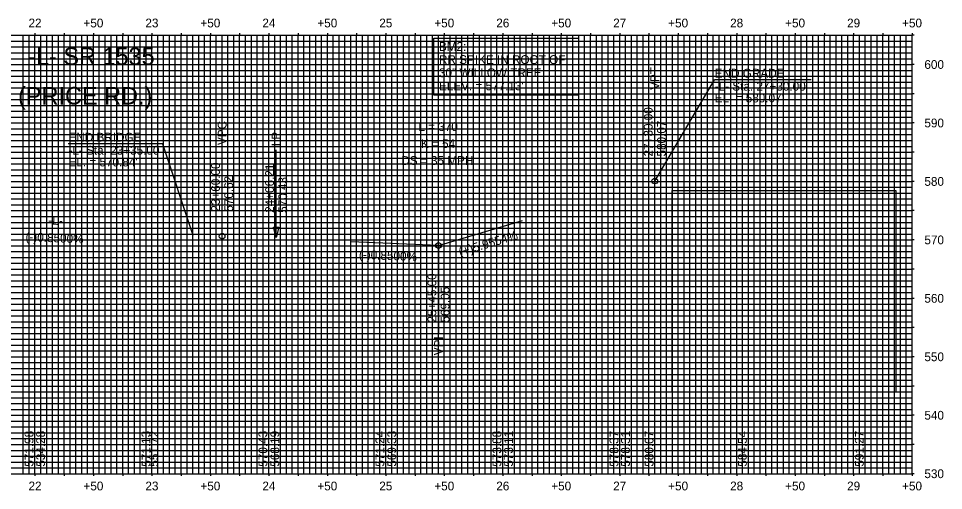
# Model space of a CAD drawing. Extents: x 523 to 1977, y 516 to 919.
# Drawn here: x 1186 to 1977, y 516 to 919 of the extents above; entities that cross this region are included whole.
import ezdxf

# ---------------------------------------------------------------- set-up
doc = ezdxf.new("R2010")
doc.units = 0
for name, color, linetype in [('_CIVIL_CONSTRUCTION', 7, 'Continuous'), ('E_ENV_WETLAND_BOUNDARY', 7, 'Continuous'), ('E_NCDOT_Vertical_Profile_Ground_Line', 7, 'Continuous'), ('Exist Hydro Jurisdictional Stream or Body of Water', 7, 'Continuous'), ('P_NCDOT_Horizontal_Alignment_Curve_and_Spiral_Data', 7, 'Continuous'), ('P_NCDOT_Horizontal_Alignment_Direction_Label', 7, 'Continuous'), ('P_NCDOT_Horizontal_Alignment_Station_Label', 7, 'Continuous'), ('P_NCDOT_Intersecting_Profile', 7, 'Continuous'), ('P_NCDOT_Vertical_Profile_Grade', 7, 'Continuous'), ('Scratch_Level_2', 7, 'Continuous'), ('Scratch_Level_4', 7, 'Continuous')]:
    doc.layers.add(name, color=color, linetype=linetype)

msp = doc.modelspace()

# ---------------------------------------------------------------- linework, layer by layer
at = {"layer": 'E_ENV_WETLAND_BOUNDARY'}
for p, q in [((1730, 780.35), (1781.08, 866.98)), ((1863.58, 866.98), (1781.08, 866.98)), ((1730, 780.35), (1730, 855.35)), ((1308.95, 812.23), (1228.48, 812.23)), ((1308.95, 812.23), (1335.05, 734.18)), ((1360, 733.12), (1360, 808.12)), ((1406.21, 732.14), (1406.21, 807.14)), ((1730, 780.35), (1730, 780.35)), ((1545, 725.26), (1616.88, 746.67)), ((1360, 733.12), (1360, 733.12)), ((1545, 725.26), (1470.07, 728.45)), ((1545, 725.26), (1545, 725.26)), ((1545, 725.26), (1545, 650.26))]:
    msp.add_line(p, q, dxfattribs=at)
for points in [[(1541.14, 902.67), (1664.63, 902.67), (1664.63, 853.75), (1541.14, 853.75)], [(1744.94, 772.35), (1936.19, 772.35), (1936.19, 599.89), (1744.94, 599.89)], [(1406.21, 732.14), (1404.03, 740.87), (1408.4, 740.87)]]:
    msp.add_lwpolyline(points, close=True, dxfattribs=at)
for centre in [(1730, 780.35), (1360, 733.12), (1545, 725.26)]:
    msp.add_circle(centre, 2.43, dxfattribs=at)
at = {"layer": 'E_NCDOT_Vertical_Profile_Ground_Line'}
for p, q in [((1200, 530), (1200, 905)), ((1250, 530), (1250, 905)), ((1300, 530), (1300, 905)), ((1350, 530), (1350, 905)), ((1400, 530), (1400, 905)), ((1450, 530), (1450, 905)), ((1500, 530), (1500, 905)), ((1550, 530), (1550, 905)), ((1600, 530), (1600, 905)), ((1650, 530), (1650, 905)), ((1700, 530), (1700, 905)), ((1750, 530), (1750, 905)), ((1800, 530), (1800, 905)), ((1850, 530), (1850, 905)), ((1900, 530), (1900, 905)), ((550, 880), (1950, 880)), ((550, 830), (1950, 830)), ((550, 780), (1950, 780)), ((550, 730), (1950, 730)), ((550, 680), (1950, 680)), ((550, 630), (1950, 630)), ((550, 580), (1950, 580))]:
    msp.add_line(p, q, dxfattribs=at)
at = {"layer": 'P_NCDOT_Horizontal_Alignment_Curve_and_Spiral_Data'}
for p, q in [((1190, 530), (1190, 905)), ((1195, 530), (1195, 905)), ((1205, 530), (1205, 905)), ((1210, 530), (1210, 905)), ((1215, 530), (1215, 905)), ((1220, 530), (1220, 905)), ((1230, 530), (1230, 905)), ((1235, 530), (1235, 905)), ((1240, 530), (1240, 905)), ((1245, 530), (1245, 905)), ((1255, 530), (1255, 905)), ((1260, 530), (1260, 905)), ((1265, 530), (1265, 905)), ((1270, 530), (1270, 905)), ((1280, 530), (1280, 905)), ((1285, 530), (1285, 905)), ((1290, 530), (1290, 905)), ((1295, 530), (1295, 905)), ((1305, 530), (1305, 905)), ((1310, 530), (1310, 905)), ((1315, 530), (1315, 905)), ((1320, 530), (1320, 905)), ((1330, 530), (1330, 905)), ((1335, 530), (1335, 905)), ((1340, 530), (1340, 905)), ((1345, 530), (1345, 905)), ((1355, 530), (1355, 905)), ((1360, 530), (1360, 905)), ((1365, 530), (1365, 905)), ((1370, 530), (1370, 905)), ((1380, 530), (1380, 905)), ((1385, 530), (1385, 905)), ((1390, 530), (1390, 905)), ((1395, 530), (1395, 905)), ((1405, 530), (1405, 905)), ((1410, 530), (1410, 905)), ((1415, 530), (1415, 905)), ((1420, 530), (1420, 905)), ((1430, 530), (1430, 905)), ((1435, 530), (1435, 905)), ((1440, 530), (1440, 905)), ((1445, 530), (1445, 905)), ((1455, 530), (1455, 905)), ((1460, 530), (1460, 905)), ((1465, 530), (1465, 905)), ((1470, 530), (1470, 905)), ((1480, 530), (1480, 905)), ((1485, 530), (1485, 905)), ((1490, 530), (1490, 905)), ((1495, 530), (1495, 905)), ((1505, 530), (1505, 905)), ((1510, 530), (1510, 905)), ((1515, 530), (1515, 905)), ((1520, 530), (1520, 905)), ((1530, 530), (1530, 905)), ((1535, 530), (1535, 905)), ((1540, 530), (1540, 905)), ((1545, 530), (1545, 905)), ((1555, 530), (1555, 905)), ((1560, 530), (1560, 905)), ((1565, 530), (1565, 905)), ((1570, 530), (1570, 905)), ((1580, 530), (1580, 905)), ((1585, 530), (1585, 905)), ((1590, 530), (1590, 905)), ((1595, 530), (1595, 905)), ((1605, 530), (1605, 905)), ((1610, 530), (1610, 905)), ((1615, 530), (1615, 905)), ((1620, 530), (1620, 905)), ((1630, 530), (1630, 905)), ((1635, 530), (1635, 905)), ((1640, 530), (1640, 905)), ((1645, 530), (1645, 905)), ((1655, 530), (1655, 905)), ((1660, 530), (1660, 905)), ((1665, 530), (1665, 905)), ((1670, 530), (1670, 905)), ((1680, 530), (1680, 905)), ((1685, 530), (1685, 905)), ((1690, 530), (1690, 905)), ((1695, 530), (1695, 905)), ((1705, 530), (1705, 905)), ((1710, 530), (1710, 905)), ((1715, 530), (1715, 905)), ((1720, 530), (1720, 905)), ((1730, 530), (1730, 905)), ((1735, 530), (1735, 905)), ((1740, 530), (1740, 905)), ((1745, 530), (1745, 905)), ((1755, 530), (1755, 905)), ((1760, 530), (1760, 905)), ((1765, 530), (1765, 905)), ((1770, 530), (1770, 905)), ((1780, 530), (1780, 905)), ((1785, 530), (1785, 905)), ((1790, 530), (1790, 905)), ((1795, 530), (1795, 905)), ((1805, 530), (1805, 905)), ((1810, 530), (1810, 905)), ((1815, 530), (1815, 905)), ((1820, 530), (1820, 905)), ((1830, 530), (1830, 905)), ((1835, 530), (1835, 905)), ((1840, 530), (1840, 905)), ((1845, 530), (1845, 905)), ((1855, 530), (1855, 905)), ((1860, 530), (1860, 905)), ((1865, 530), (1865, 905)), ((1870, 530), (1870, 905)), ((1880, 530), (1880, 905)), ((1885, 530), (1885, 905)), ((1890, 530), (1890, 905)), ((1895, 530), (1895, 905)), ((1905, 530), (1905, 905)), ((1910, 530), (1910, 905)), ((1915, 530), (1915, 905)), ((1920, 530), (1920, 905)), ((1930, 530), (1930, 905)), ((1935, 530), (1935, 905)), ((1940, 530), (1940, 905)), ((1945, 530), (1945, 905)), ((550, 900), (1950, 900)), ((550, 895), (1950, 895)), ((550, 890), (1950, 890)), ((550, 885), (1950, 885)), ((550, 875), (1950, 875)), ((550, 870), (1950, 870)), ((550, 865), (1950, 865)), ((550, 860), (1950, 860)), ((550, 850), (1950, 850)), ((550, 845), (1950, 845)), ((550, 840), (1950, 840)), ((550, 835), (1950, 835)), ((550, 825), (1950, 825)), ((550, 820), (1950, 820)), ((550, 815), (1950, 815)), ((550, 810), (1950, 810)), ((550, 800), (1950, 800)), ((550, 795), (1950, 795)), ((550, 790), (1950, 790)), ((550, 785), (1950, 785)), ((550, 775), (1950, 775)), ((550, 770), (1950, 770)), ((550, 765), (1950, 765)), ((550, 760), (1950, 760)), ((550, 750), (1950, 750)), ((550, 745), (1950, 745)), ((550, 740), (1950, 740)), ((550, 735), (1950, 735)), ((550, 725), (1950, 725)), ((550, 720), (1950, 720)), ((550, 715), (1950, 715)), ((550, 710), (1950, 710)), ((550, 700), (1950, 700)), ((550, 695), (1950, 695)), ((550, 690), (1950, 690)), ((550, 685), (1950, 685)), ((550, 675), (1950, 675)), ((550, 670), (1950, 670)), ((550, 665), (1950, 665)), ((550, 660), (1950, 660)), ((550, 650), (1950, 650)), ((550, 645), (1950, 645)), ((550, 640), (1950, 640)), ((550, 635), (1950, 635)), ((550, 625), (1950, 625)), ((550, 620), (1950, 620)), ((550, 615), (1950, 615)), ((550, 610), (1950, 610)), ((550, 600), (1950, 600)), ((550, 595), (1950, 595)), ((550, 590), (1950, 590)), ((550, 585), (1950, 585)), ((550, 575), (1950, 575)), ((550, 570), (1950, 570)), ((550, 565), (1950, 565)), ((550, 560), (1950, 560)), ((550, 550), (1950, 550)), ((550, 545), (1950, 545)), ((550, 540), (1950, 540)), ((550, 535), (1950, 535))]:
    msp.add_line(p, q, dxfattribs=at)
at = {"layer": 'P_NCDOT_Horizontal_Alignment_Direction_Label'}
for p, q in [((1200, 906.8), (1200, 905)), ((1200, 530), (1200, 905)), ((1225, 906.8), (1225, 905)), ((1225, 530), (1225, 905)), ((1250, 906.8), (1250, 905)), ((1250, 530), (1250, 905)), ((1275, 906.8), (1275, 905)), ((1275, 530), (1275, 905)), ((1300, 906.8), (1300, 905)), ((1300, 530), (1300, 905)), ((1325, 906.8), (1325, 905)), ((1325, 530), (1325, 905)), ((1350, 906.8), (1350, 905)), ((1350, 530), (1350, 905)), ((1375, 906.8), (1375, 905)), ((1375, 530), (1375, 905)), ((1400, 906.8), (1400, 905)), ((1400, 530), (1400, 905)), ((1425, 906.8), (1425, 905)), ((1425, 530), (1425, 905)), ((1450, 906.8), (1450, 905)), ((1450, 530), (1450, 905)), ((1475, 906.8), (1475, 905)), ((1475, 530), (1475, 905)), ((1500, 906.8), (1500, 905)), ((1500, 530), (1500, 905)), ((1525, 906.8), (1525, 905)), ((1525, 530), (1525, 905)), ((1550, 906.8), (1550, 905)), ((1550, 530), (1550, 905)), ((1575, 906.8), (1575, 905)), ((1575, 530), (1575, 905)), ((1600, 906.8), (1600, 905)), ((1600, 530), (1600, 905)), ((1625, 906.8), (1625, 905)), ((1625, 530), (1625, 905)), ((1650, 906.8), (1650, 905)), ((1650, 530), (1650, 905)), ((1675, 906.8), (1675, 905)), ((1675, 530), (1675, 905)), ((1700, 906.8), (1700, 905)), ((1700, 530), (1700, 905)), ((1725, 906.8), (1725, 905)), ((1725, 530), (1725, 905)), ((1750, 906.8), (1750, 905)), ((1750, 530), (1750, 905)), ((1775, 906.8), (1775, 905)), ((1775, 530), (1775, 905)), ((1800, 906.8), (1800, 905)), ((1800, 530), (1800, 905)), ((1825, 906.8), (1825, 905)), ((1825, 530), (1825, 905)), ((1850, 906.8), (1850, 905)), ((1850, 530), (1850, 905)), ((1875, 906.8), (1875, 905)), ((1875, 530), (1875, 905)), ((1900, 906.8), (1900, 905)), ((1900, 530), (1900, 905)), ((1925, 906.8), (1925, 905)), ((1925, 530), (1925, 905)), ((1950, 906.8), (1950, 905)), ((1951.8, 905), (1950, 905)), ((550, 880), (1950, 880)), ((1951.8, 880), (1950, 880)), ((550, 855), (1950, 855)), ((1951.8, 855), (1950, 855)), ((550, 830), (1950, 830)), ((1951.8, 830), (1950, 830)), ((550, 805), (1950, 805)), ((1951.8, 805), (1950, 805)), ((550, 780), (1950, 780)), ((1951.8, 780), (1950, 780)), ((550, 755), (1950, 755)), ((1951.8, 755), (1950, 755)), ((550, 730), (1950, 730)), ((1951.8, 730), (1950, 730)), ((550, 705), (1950, 705)), ((1951.8, 705), (1950, 705)), ((550, 680), (1950, 680)), ((1951.8, 680), (1950, 680)), ((550, 655), (1950, 655)), ((1951.8, 655), (1950, 655)), ((550, 630), (1950, 630)), ((1951.8, 630), (1950, 630)), ((550, 605), (1950, 605)), ((1951.8, 605), (1950, 605)), ((550, 580), (1950, 580)), ((1951.8, 580), (1950, 580)), ((550, 555), (1950, 555)), ((1951.8, 555), (1950, 555)), ((1200, 530), (1200, 528.2)), ((1225, 530), (1225, 528.2)), ((1250, 530), (1250, 528.2)), ((1275, 530), (1275, 528.2)), ((1300, 530), (1300, 528.2)), ((1325, 530), (1325, 528.2)), ((1350, 530), (1350, 528.2)), ((1375, 530), (1375, 528.2)), ((1400, 530), (1400, 528.2)), ((1425, 530), (1425, 528.2)), ((1450, 530), (1450, 528.2)), ((1475, 530), (1475, 528.2)), ((1500, 530), (1500, 528.2)), ((1525, 530), (1525, 528.2)), ((1550, 530), (1550, 528.2)), ((1575, 530), (1575, 528.2)), ((1600, 530), (1600, 528.2)), ((1625, 530), (1625, 528.2)), ((1650, 530), (1650, 528.2)), ((1675, 530), (1675, 528.2)), ((1700, 530), (1700, 528.2)), ((1725, 530), (1725, 528.2)), ((1750, 530), (1750, 528.2)), ((1775, 530), (1775, 528.2)), ((1800, 530), (1800, 528.2)), ((1825, 530), (1825, 528.2)), ((1850, 530), (1850, 528.2)), ((1875, 530), (1875, 528.2)), ((1900, 530), (1900, 528.2)), ((1925, 530), (1925, 528.2)), ((1950, 530), (1950, 528.2)), ((1951.8, 530), (1950, 530))]:
    msp.add_line(p, q, dxfattribs=at)
at = {"layer": 'P_NCDOT_Horizontal_Alignment_Station_Label'}
for p, q in [((550, 905), (1950, 905)), ((1950, 530), (1950, 905)), ((550, 530), (1950, 530))]:
    msp.add_line(p, q, dxfattribs=at)

# ---------------------------------------------------------------- texts
at = {"layer": '_CIVIL_CONSTRUCTION'}
for s, p in [('-', (1211.11, 743.2)), ('L', (1214.59, 743.05)), ('-', (1220.41, 742.8)), ('(-)0.8500%', (1191.78, 729.02))]:
    msp.add_text(s, height=7.5, rotation=357.56639, dxfattribs=at).set_placement(p)
at = {"layer": 'E_ENV_WETLAND_BOUNDARY'}
for s, p in [('BM2:', (1545.42, 891.7)), ('RR SPIKE IN ROOT OF', (1545.42, 880.45)), ('30" WILLOW TREE', (1545.42, 869.2)), ("ELEV. = 577.13'", (1545.42, 857.95))]:
    msp.add_text(s, height=7.5, dxfattribs=at).set_placement(p)
for s, rotation, p in [('VPT', 90, (1733.75, 858.35)), ('END GRADE', 360, (1781.24, 868.82)), ('-L- Sta. 27+30.00', 360, (1781.24, 857.66)), ("EL. = 580.07'", 360, (1781.24, 847.6)), ('27+30.00', 90, (1728.13, 801.35)), ('VPC', 90, (1363.75, 811.12)), ('580.07', 90, (1739.38, 801.35)), ('END BRIDGE', 360, (1228.64, 814.08)), ('LP', 90, (1409.96, 810.14)), ('LP', 90, (1409.96, 810.14)), ('-L- Sta. 23+35.00', 360, (1228.64, 802.91)), ("EL. = 570.84'", 360, (1228.64, 792.85)), ('23+60.00', 90, (1358.13, 754.12)), ('24+06.21', 90, (1404.34, 753.14)), ('24+06.21', 90, (1404.34, 753.14)), ('570.62', 90, (1369.38, 754.12)), ('570.43', 90, (1415.59, 753.14)), ('570.43', 90, (1415.59, 753.14)), ('(+)5.9554%', 16.58207, (1563.54, 715.91)), ('(-)0.8500%', 357.56639, (1476.87, 713.89)), ('25+45.00', 90, (1543.13, 659.26)), ('569.05', 90, (1554.38, 659.26)), ('VPI', 90, (1548.75, 631.31))]:
    msp.add_text(s, height=7.5, rotation=rotation, dxfattribs=at).set_placement(p)
at = {"layer": 'Exist Hydro Jurisdictional Stream or Body of Water'}
for s, p in [('534.28', (1208.59, 536)), ('551.72', (1305.42, 536)), ('568.19', (1408.84, 536)), ('569.33', (1508.81, 536)), ('573.11', (1608.71, 536)), ('578.31', (1708.66, 536)), ('584.54', (1808.59, 536)), ('591.27', (1908.62, 536))]:
    msp.add_text(s, height=7.5, rotation=90, dxfattribs=at).set_placement(p)
at = {"layer": 'P_NCDOT_Intersecting_Profile'}
for s, height, p in [('-L- SR 1535', 15, (1194.17, 879.54)), ('(PRICE RD.)', 15, (1185.55, 845.79)), ('L = 370', 7.5, (1527.83, 823.13)), ('K = 54', 7.5, (1529.97, 808.63)), ('DS = 35 MPH', 7.5, (1513.25, 794.13))]:
    msp.add_text(s, height=height, dxfattribs=at).set_placement(p)
at = {"layer": 'P_NCDOT_Vertical_Profile_Grade'}
for s, p in [('22', (1194.45, 911.75)), ('+50', (1241.46, 911.75)), ('23', (1294.41, 911.75)), ('+50', (1341.46, 911.75)), ('24', (1394.43, 911.75)), ('+50', (1441.46, 911.75)), ('25', (1494.38, 911.75)), ('+50', (1541.46, 911.75)), ('26', (1594.41, 911.75)), ('+50', (1641.46, 911.75)), ('27', (1694.41, 911.75)), ('+50', (1741.46, 911.75)), ('28', (1794.41, 911.75)), ('+50', (1841.46, 911.75)), ('29', (1894.41, 911.75)), ('+50', (1941.46, 911.75)), ('22', (1194.45, 515.75)), ('+50', (1241.46, 515.75)), ('23', (1294.41, 515.75)), ('+50', (1341.46, 515.75)), ('24', (1394.43, 515.75)), ('+50', (1441.46, 515.75)), ('25', (1494.38, 515.75)), ('+50', (1541.46, 515.75)), ('26', (1594.41, 515.75)), ('+50', (1641.46, 515.75)), ('27', (1694.41, 515.75)), ('+50', (1741.46, 515.75)), ('28', (1794.41, 515.75)), ('+50', (1841.46, 515.75)), ('29', (1894.41, 515.75)), ('+50', (1941.46, 515.75))]:
    msp.add_text(s, height=7.5, dxfattribs=at).set_placement(p)
at = {"layer": 'Scratch_Level_2'}
for s, p in [('600', (1960.5, 876.25)), ('590', (1960.5, 826.25)), ('580', (1960.5, 776.25)), ('570', (1960.5, 726.25)), ('560', (1960.5, 676.25)), ('550', (1960.5, 626.25)), ('540', (1960.5, 576.25)), ('530', (1960.5, 526.25))]:
    msp.add_text(s, height=7.5, dxfattribs=at).set_placement(p)
at = {"layer": 'Scratch_Level_4'}
for s, p in [('571.98', (1198.65, 536)), ('571.13', (1298.65, 536)), ('570.43', (1398.65, 536)), ('571.24', (1498.67, 536)), ('573.88', (1598.73, 536)), ('578.37', (1698.83, 536)), ('580.07', (1728.86, 536))]:
    msp.add_text(s, height=7.5, rotation=90, dxfattribs=at).set_placement(p)

doc.saveas('drawing.dxf')
